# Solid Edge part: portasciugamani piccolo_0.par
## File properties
Last saved by: i.fialdini
Revision: 62
Tipo di contenuto documento: 0
Accuracy: 0.990
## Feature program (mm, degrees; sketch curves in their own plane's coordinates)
body "unnamed Body 1"
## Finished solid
Body 1: solid body, 3 faces, 4 edges, 4 vertices.
  Faces by surface: cylinder 3
  Edges by curve: ellipse 4
Bounding box of the edges (mm): 490.000 x 21.000 x 21.000, from (-245, 167.5, -167.5) to (245, 188.5, -146.5).
Cylindrical faces by radius (mm): R10.5 x3
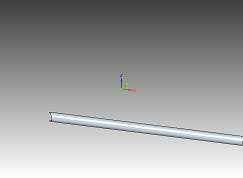
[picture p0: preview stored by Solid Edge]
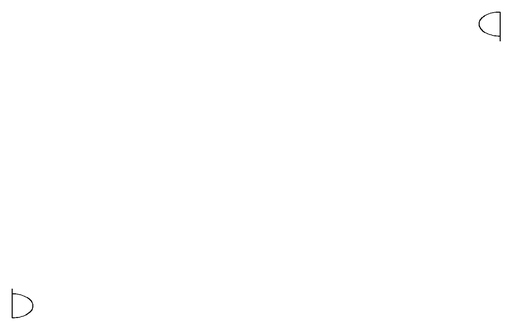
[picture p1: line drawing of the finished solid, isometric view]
